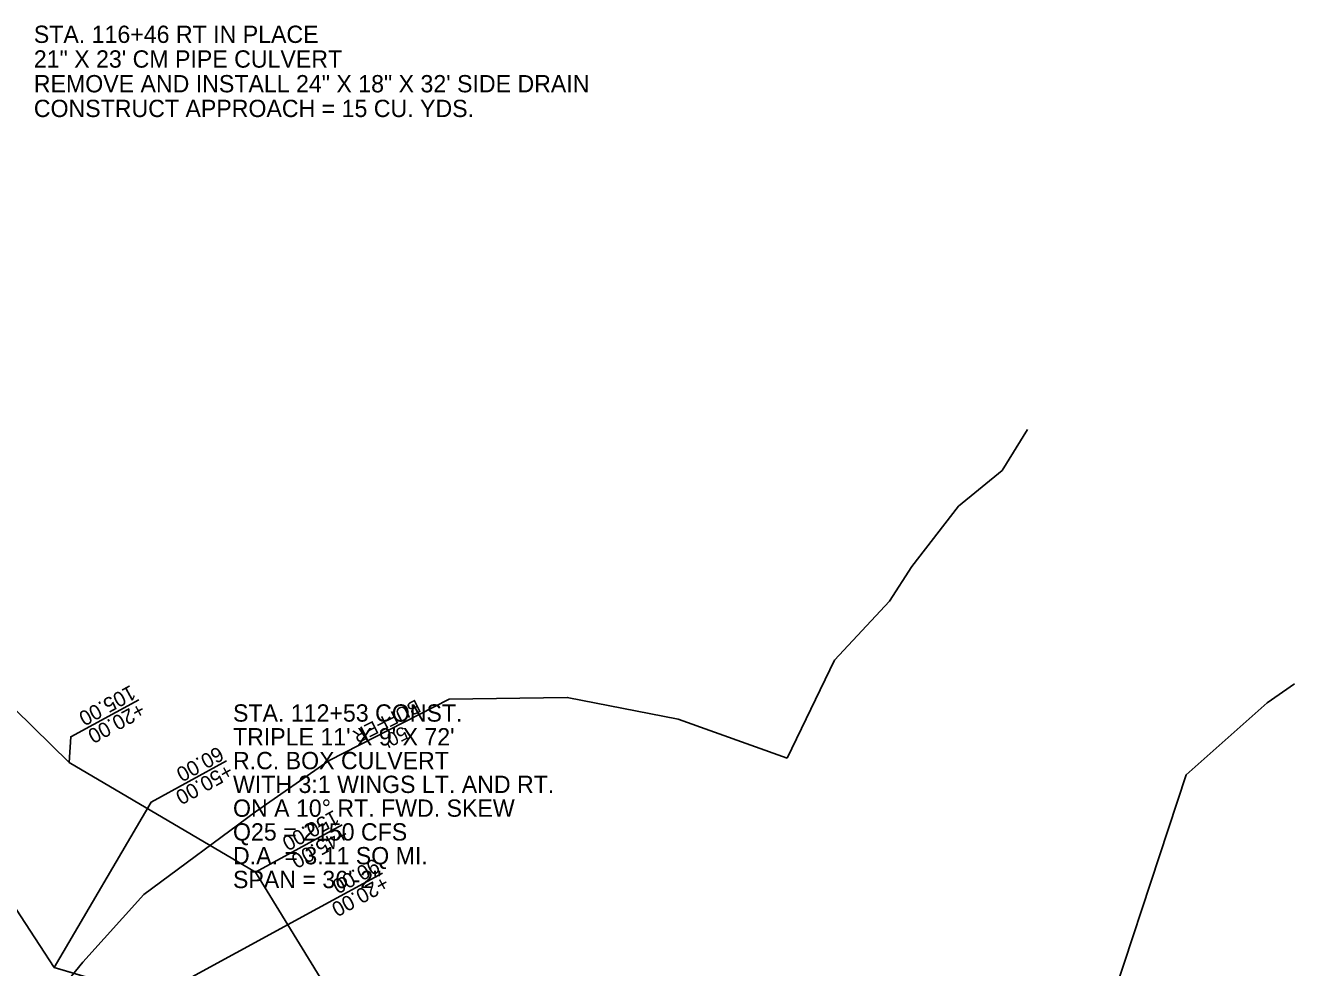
# Model space of a CAD drawing. Extents: x 1627557 to 1636561, y 783843 to 794002.
# Drawn here: x 1628047 to 1628561, y 785041 to 785422 of the extents above; entities that cross this region are included whole.
import ezdxf

# ---------------------------------------------------------------- set-up
doc = ezdxf.new("R2010")
doc.units = 0
for name, color, linetype in [('25 FT Buffer', 7, 'Continuous'), ('R_Culvert Annot', 7, 'Continuous'), ('R_ROW', 7, 'Continuous'), ('R_ROW Annot', 7, 'Continuous'), ('R_Temp Const Easement', 7, 'Continuous'), ('R_Temp Easement Annot', 7, 'Continuous'), ('RC Box Annot', 7, 'Continuous')]:
    doc.layers.add(name, color=color, linetype=linetype)

msp = doc.modelspace()

# ---------------------------------------------------------------- linework, layer by layer
at = {"layer": '25 FT Buffer'}
for points in [[(1628452.88, 785258.45), (1628442.55, 785241.94), (1628424.92, 785227.4), (1628406, 785202.99), (1628396.99, 785189.05), (1628374.77, 785165.09), (1628355.58, 785125.53)], [(1628560.94, 785155.55), (1628549.76, 785147.87), (1628517.02, 785118.79), (1628477.49, 784998.68), (1628405.7, 784961.56), (1628353.93, 784946.56), (1628317.3, 784978.64), (1628300.57, 784991.85), (1628269.43, 784998.1), (1628252.11, 785001.38), (1628241.51, 785002.7), (1628233.9, 784999.54), (1628206.02, 784986.66), (1628193.93, 784976.66), (1628193.21, 784975.34), (1628183.18, 784944.53), (1628141.61, 784911.68), (1628128.73, 784912.02)], [(1628355.58, 785125.53), (1628311.46, 785141.24), (1628266.6, 785150.06), (1628218.83, 785149.33), (1628170.24, 785124.54), (1628140.43, 785103.8), (1628095.21, 785070.36), (1628070.53, 785042.96), (1628054.55, 785023.15)], [(1628198.17, 784774.92), (1628099.65, 785028.73), (1628058.95, 785040.71)]]:
    msp.add_lwpolyline(points, dxfattribs=at)
at = {"layer": 'R_ROW'}
for p, q in [((1628058.95, 785040.71), (1627921.72, 785250.62)), ((1628099.65, 785028.73), (1628058.95, 785040.71))]:
    msp.add_line(p, q, dxfattribs=at)
at = {"layer": 'R_ROW Annot'}
for points in [[(1628058.95, 785040.71), (1628098.25, 785107.7), (1628128.74, 785124.33)], [(1628099.65, 785028.73), (1628165.5, 785064.63), (1628191.84, 785078.99)]]:
    msp.add_lwpolyline(points, dxfattribs=at)
at = {"layer": 'R_Temp Const Easement'}
for p, q in [((1628064.95, 785123.71), (1627930.5, 785255.41)), ((1628140.36, 785079.4), (1628064.95, 785123.71)), ((1628190.23, 784998.39), (1628140.36, 785079.4))]:
    msp.add_line(p, q, dxfattribs=at)
at = {"layer": 'R_Temp Easement Annot'}
for points in [[(1628064.95, 785123.71), (1628065.66, 785134.11), (1628093.19, 785149.12)], [(1628140.36, 785079.4), (1628175.48, 785098.55)]]:
    msp.add_lwpolyline(points, dxfattribs=at)

# ---------------------------------------------------------------- texts
at = {"layer": '25 FT Buffer'}
for s, p in [('BUFFER', (1628205.43, 785149.44)), ("50'", (1628200.22, 785138.6))]:
    msp.add_text(s, height=5.5, rotation=206.744, dxfattribs=at).set_placement(p)
at = {"layer": 'R_Culvert Annot'}
for s, p in [('STA. 116+46 RT IN PLACE', (1628050.71, 785414.93)), ('21" X 23\' CM PIPE CULVERT', (1628050.71, 785404.93)), ('REMOVE AND INSTALL 24" X 18" X 32\' SIDE DRAIN', (1628050.71, 785394.93)), ('CONSTRUCT APPROACH = 15 CU. YDS.', (1628050.71, 785384.93))]:
    msp.add_text(s, height=7, dxfattribs=at).set_placement(p)
at = {"layer": 'R_ROW Annot'}
for s, p in [('60.00', (1628125.39, 785130.47)), ('+50.00', (1628129.22, 785123.45)), ('90.00', (1628188.49, 785085.14)), ('+20.00', (1628192.32, 785078.11))]:
    msp.add_text(s, height=6, rotation=208.601, dxfattribs=at).set_placement(p)
at = {"layer": 'R_Temp Easement Annot'}
for s, p in [('105.00', (1628089.84, 785155.26)), ('+20.00', (1628093.67, 785148.24)), ('150.00', (1628172.13, 785104.69)), ('+45.00', (1628175.96, 785097.67))]:
    msp.add_text(s, height=6, rotation=208.601, dxfattribs=at).set_placement(p)
at = {"layer": 'RC Box Annot'}
for s, p in [('STA. 112+53 CONST.', (1628131.31, 785140.25)), ("TRIPLE 11' X 9' X 72'", (1628131.31, 785130.63)), ('R.C. BOX CULVERT', (1628131.31, 785121)), ('WITH 3:1 WINGS LT. AND RT.', (1628131.31, 785111.38)), ('ON A 10%%D RT. FWD. SKEW', (1628131.31, 785101.75)), ('Q25 = 2150 CFS', (1628131.31, 785092.13)), ('D.A. = 3.11 SQ MI.', (1628131.31, 785082.5)), ('SPAN = 36\'-2"', (1628131.31, 785072.88))]:
    msp.add_text(s, height=7, dxfattribs=at).set_placement(p)

doc.saveas('drawing.dxf')
